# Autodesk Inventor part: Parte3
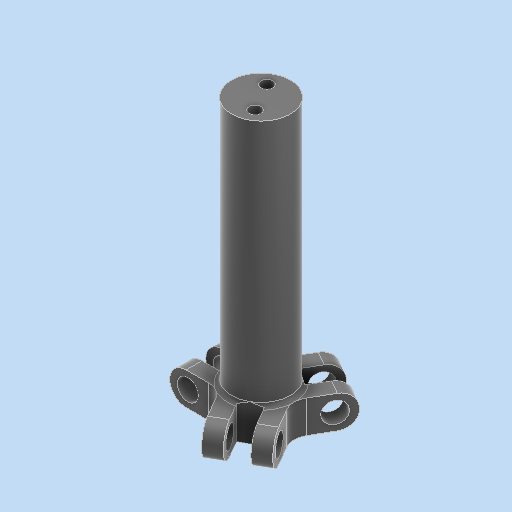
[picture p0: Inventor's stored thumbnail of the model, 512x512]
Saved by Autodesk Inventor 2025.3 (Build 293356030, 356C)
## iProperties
Created: 2026-05
Part Number: Parte3
Material: Generico
Document SubType Name: Modeling
Designer: Ryzen5700u
Density: 1 g/cm^3
Appearance: Liscia - Nero
Author: Ryzen5700u
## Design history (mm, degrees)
sketch "Schizzo1"
  geometry: L1 (0, 4)-(10, 4); L2 (10, 4)-(10, -4); L3 (10, -4)-(0, -4); L4 (-10, 4)-(10, -4); L5 (10, 4)-(-10, -4); L6 (-8.464, 6.66)-(-1.536, 10.66); L7 (-1.536, 10.66)-(3.464, 2); L8 (-3.464, -2)-(-8.464, 6.66); L9 (-1.536, -10.66)-(-8.464, -6.66); L10 (-8.464, -6.66)-(-3.464, 2); L11 (3.464, -2)-(-1.536, -10.66); A1 r 4 centre (0, 0) between (0, 4) and (0, -4); 19 further points
  constraints: 22 end point, 2 midpoint, 2 point on circle, 1 centre point, 1 coincident, 1 horizontal, 1 parallel, 1 perpendicular, 22 other
  dimensions: "d0" = 8 diameter of A1; "d2" = 8 distance of L1.end L2.end; "d5" = 360 deg dimension on point (0, 0) L2.end (derived); "d28" = 10 distance from line of point (0, 0) L2
extrude "Estrusione1" new body sketch "Schizzo1" distance "d7" = 5; taper "d8" = 0 deg
sketch "Schizzo2"
  geometry: L1 (0, 0)-(-8.669, 0); L2 (-10, 4)-(-10, -4) reference; L3 (-15.5, -1.55)-(-4.5, -1.55); L4 (-4.5, -1.55)-(-4.5, 1.55); L5 (-4.5, 1.55)-(-15.5, 1.55); L6 (-15.5, 1.55)-(-15.5, -1.55); L7 (-15.5, -1.55)-(-4.5, 1.55); L8 (-4.5, -1.55)-(-15.5, 1.55); 3 further points
  constraints: 14 end point, 3 midpoint, 2 horizontal, 2 parallel, 1 perpendicular
  dimensions: "d9" = 11 distance of L5.end L4.end; "d10" = 3.1 distance of L4.end L3.end
extrude "Estrusione2" cut sketch "Schizzo2" extent not by distance; stored distance "d11" = 0; taper "d12" = 0 deg
pattern_circular "Serie circolare1" dims angle "d14" = 360 deg
sketch "Schizzo3"
  geometry: L1 (5.5, 5)-(5.5, 0) reference; L2 (0, 0)-(0, 5) reference; L3 (0, 5)-(5.5, 0); 2 further points
  constraints: 2 end point, 1 midpoint
hole "Foro1" sketch "Schizzo3" at (2.75, 2.5) diameter "d16" = 3.2; stored, may be unused: countersink angle "d20" = 90 deg, drill point angle "d22" = 118 deg; dims "d17" = 4, "d18" = 32, "d19" = 10, "d21" = 8
pattern_circular "Serie circolare2" dims angle "d24" = 360 deg
sketch "Schizzo4"
  geometry: C1 r 4.5 at (0, 0); 1 further point
  constraints: 1 centre point, 1 coincident
  dimensions: "d29" = 9 diameter of C1
extrude "Estrusione3" join sketch "Schizzo4" distance "d26" = 38; taper "d27" = 0 deg
fillet "Raccordo1" dims "d30" = 2.5
fillet "Raccordo2" dims "d31" = 0.6
fillet "Raccordo3" dims "d32" = 3
sketch "Schizzo5"
  geometry: C1 r 4.5 at (0, 0) reference; 2 further points
  constraints: 1 coincident
hole "Foro2" sketch "Schizzo5" at (0, 0) diameter "d33" = 2.2; stored, may be unused: countersink angle "d37" = 90 deg, drill point angle "d39" = 118 deg; dims "d34" = 6, "d35" = 4.4, "d36" = 2.3, "d38" = 15
sketch "Schizzo6"
  geometry: L1 (43, -4.5)-(43, 4.5) reference; L2 (5.6, 3.897)-(5.6, 0) reference; L3 (5.6, 0)-(5.6, -3.897) reference; L4 (5.6, -3.897)-(5.6, 3.897) reference; C1 r 3 at (43, 0); 6 further points
  constraints: 1 centre point, 1 midpoint, 3 other
  dimensions: "d40" = 1.5 dimension on C1
extrude "Estrusione4" join sketch "Schizzo6" stored distance "d41" = 3; taper "d42" = 0 deg
sketch "Schizzo7"
  geometry: C1 r 4.5 at (0, 0) reference; C2 r 4 at (0, 0); C3 r 4.307 at (0, 0); 3 further points
  constraints: 2 centre point, 1 coincident
extrude "Estrusione5" cut sketch "Schizzo7" distance "d43" = 18.25; taper "d44" = 0 deg
fillet "Raccordo4" dims "d45" = 1
fillet "Raccordo5" dims "d46" = 0.4
sketch "Schizzo8"
  geometry: C1 r 0.9 at (1.25, -2.165) reference; C2 r 0.9 at (-1.25, 2.165) reference; 1 further point
hole "Foro3" sketch "Schizzo8" at (1.25, -2.165), (-1.25, 2.165) diameter "d47" = 1.8; stored, may be unused: countersink angle "d51" = 90 deg, drill point angle "d53" = 118 deg; dims "d48" = 6, "d49" = 3.5, "d50" = 1, "d52" = 15
feature "ǉ耀ǋ耀Ǎ耀Ǐ耀Ǒ耀Ǔ耀Ǖ耀Ǘ耀" dims "d0" = 8, "d2" = 8, "d3" = 30, "d5" = 360 deg (derived), "d7" = 5, "d8" = 0, "d9" = 11, "d10" = 3.1, "d11" = 0, "d12" = 0, "d13" = 30, "d14" = 360 deg, "d16" = 3.2, "d17" = 4, "d18" = 32, "d19" = 10, "d20" = 90 deg, "d21" = 8, "d22" = 118 deg, "d23" = 30, "d24" = 360 deg, "d26" = 38, "d27" = 0, "d28" = 10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
node "Solido1"
node "Schizzo - Serie circolare1" dims "d5" = 360 deg (derived)
node "Linea chiusa proiettata1"
node "Linea chiusa proiettata2"
node "Riferimento1"
node "Riferimento2"
